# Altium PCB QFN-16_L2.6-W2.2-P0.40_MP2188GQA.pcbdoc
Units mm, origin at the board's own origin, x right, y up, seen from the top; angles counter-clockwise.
Board outline 15.62 x 15.78 mm, 2 copper layers (Top Layer, Bottom Layer), stack 0 mm thick; 1 components, 0 nets, 16 pads, 0 vias.
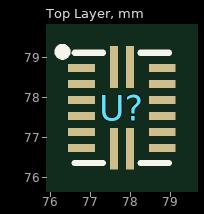
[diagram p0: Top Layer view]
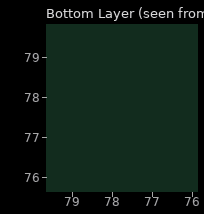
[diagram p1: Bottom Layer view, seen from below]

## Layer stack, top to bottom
Top Layer: signal copper (thickness not stored)
Bottom Layer: signal copper (thickness not stored)

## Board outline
85.47,69.85 69.85,69.85 69.85,85.63 85.47,85.63

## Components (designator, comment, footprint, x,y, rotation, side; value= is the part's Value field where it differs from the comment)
U? "" QFN-16_L2.6-W2.2-P0.40_MP2188GQA 77.78,77.74 r0 top

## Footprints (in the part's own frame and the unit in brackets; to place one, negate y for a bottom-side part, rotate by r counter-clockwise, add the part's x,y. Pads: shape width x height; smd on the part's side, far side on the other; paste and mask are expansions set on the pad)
QFN-16_L2.6-W2.2-P0.40_MP2188GQA [mm]
  rect 0.665x0.2 smd: 1(-1.008,1) 2(-1.008,0.6) 3(-1.008,0.2) 4(-1.008,-0.2) 5(-1.008,-0.6) 6(-1.008,-1) 9(1.008,-1) 10(1.008,-0.6) 11(1.008,-0.2) 12(1.008,0.2) 13(1.008,0.6) 14(1.008,1)
  rect 0.2x1.04 smd: 7(-0.2,-1.02) 8(0.2,-1.02) 15(0.2,1.02) 16(-0.2,1.02)
  silkscreen extent -1.58,-1.38 1.18,1.5

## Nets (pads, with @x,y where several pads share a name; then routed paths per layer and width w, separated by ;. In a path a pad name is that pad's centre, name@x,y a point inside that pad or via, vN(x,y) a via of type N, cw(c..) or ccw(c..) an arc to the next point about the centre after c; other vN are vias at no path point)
pads on no net: U?.1 U?.2 U?.3 U?.4 U?.5 U?.6 U?.7 U?.8 U?.9 U?.10 U?.11 U?.12 U?.13 U?.14 U?.15 U?.16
